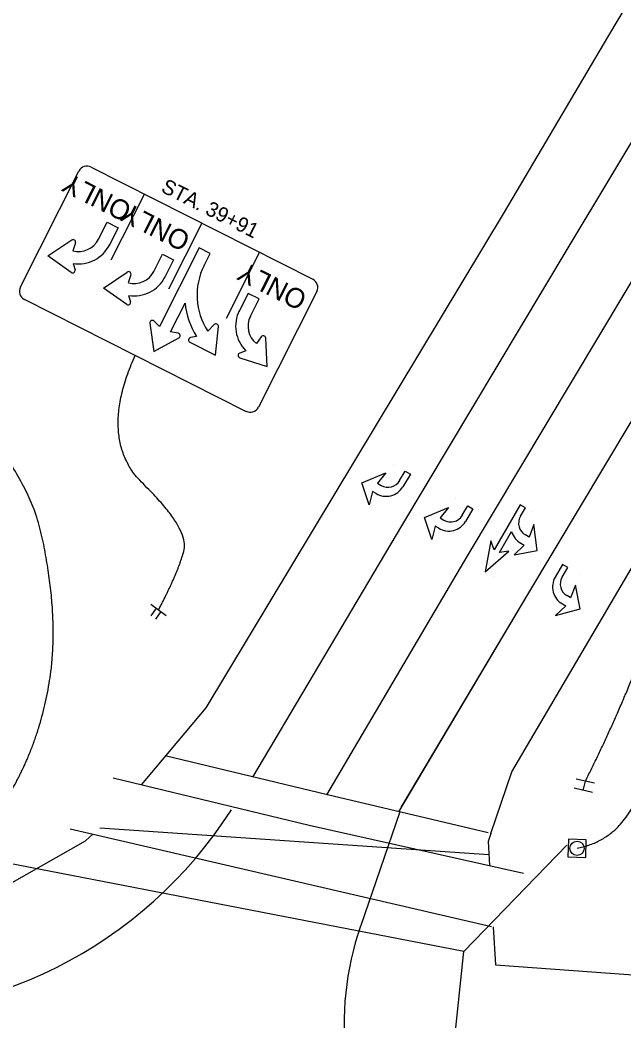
# Model space of a CAD drawing. Extents: x 1847379 to 1850904, y 217032 to 220169.
# Drawn here: x 1848879.8 to 1848981.8, y 218877.1 to 219045.9 of the extents above; entities that cross this region are included whole.
import ezdxf

# ---------------------------------------------------------------- set-up
doc = ezdxf.new("R2010")
doc.units = 0
for name, color, linetype in [('BR_P_Gen_Approach_Slab_Hidden', 7, 'Continuous'), ('BR_P_Gen_Phase_Construction', 7, 'Continuous'), ('PM_P_Cells', 7, 'Continuous'), ('PM_P_Crosswalk', 7, 'Continuous'), ('PM_P_Dotted_Line', 7, 'Continuous'), ('PM_P_Edge_Line', 7, 'Continuous'), ('PM_P_Stop_Line', 7, 'Continuous'), ('PM_X_Cells', 7, 'Continuous'), ('PM_X_Channelizing_Line', 7, 'Continuous'), ('PM_X_Dotted_Line', 7, 'Continuous'), ('PM_X_Stop_Line', 7, 'Continuous'), ('SG_X_Wiring', 7, 'Continuous'), ('SN_X_Foundation', 7, 'Continuous'), ('SN_X_Public', 7, 'Continuous')]:
    doc.layers.add(name, color=color, linetype=linetype)

msp = doc.modelspace()

# ---------------------------------------------------------------- linework, layer by layer
at = {"layer": 'BR_P_Gen_Approach_Slab_Hidden'}
for p, q in [((1848979.04, 219043.04), (1849023.78, 219117.99)), ((1848961.59, 219013.49), (1848979.04, 219043.04)), ((1848911.24, 218929.86), (1848961.59, 219013.49)), ((1848962.84, 218919.07), (1849001.98, 218985.74)), ((1848900.33, 218916.9), (1848911.24, 218929.86)), ((1848959.3, 218908.69), (1848962.84, 218919.07)), ((1848959.3, 218908.69), (1848958.84, 218907.32)), ((1848958.84, 218907.32), (1848959.08, 218903.27))]:
    msp.add_line(p, q, dxfattribs=at)
at = {"layer": 'BR_P_Gen_Phase_Construction'}
msp.add_line((1848893.29, 218909.66), (1848958.97, 218905.12), dxfattribs=at)
at = {"layer": 'PM_P_Cells'}
for p, q in [((1848964.26, 218964.14), (1848959.88, 218956.56)), ((1848965.13, 218963.64), (1848964.26, 218964.14)), ((1848964.29, 218962.19), (1848965.13, 218963.64)), ((1848966.14, 218963.05), (1848966.14, 218963.05)), ((1848966.57, 218960.81), (1848965.74, 218958.7)), ((1848967.12, 218956.42), (1848966.57, 218960.81)), ((1848965.74, 218958.7), (1848965.13, 218959.05)), ((1848959.31, 218958.04), (1848958.32, 218952.85)), ((1848959.88, 218956.56), (1848959.31, 218958.04)), ((1848964.94, 218957.31), (1848963.24, 218955.71)), ((1848964.36, 218957.65), (1848964.94, 218957.31)), ((1848958.32, 218952.85), (1848962.32, 218956.31)), ((1848962.32, 218956.31), (1848960.75, 218956.06)), ((1848963.24, 218955.71), (1848967.12, 218956.42)), ((1848959.76, 218952.01), (1848959.76, 218952.01))]:
    msp.add_line(p, q, dxfattribs=at)
msp.add_lwpolyline([(1848960.75, 218956.06), (1848962.8, 218959.61)], dxfattribs=at)
for centre, radius, start, end in [((1848966.28, 218961.04), 2.3, 149.9979, 239.9979), ((1848965.96, 218960.51), 3.28, 195.9514, 240.9064)]:
    msp.add_arc(centre, radius, start, end, dxfattribs=at)
at = {"layer": 'PM_P_Crosswalk'}
msp.add_line((1848888.3, 218909.46), (1848959.41, 218892.97), dxfattribs=at)
msp.add_lwpolyline([(1848895.52, 218918.05), (1848928.63, 218910.1), (1848964.8, 218901.99)], dxfattribs=at)
at = {"layer": 'PM_P_Dotted_Line'}
msp.add_line((1848943.92, 218912.31), (1848937.27, 218893.02), dxfattribs=at)
for centre, radius, start, end in [((1848852.35, 218953.13), 75, 265.9117, 327.3396), ((1848984.54, 218876.73), 50, 160.9794, 265.9392)]:
    msp.add_arc(centre, radius, start, end, dxfattribs=at)
at = {"layer": 'PM_P_Edge_Line'}
for p, q in [((1848890.9, 218907.47), (1848892.11, 218908.58)), ((1848871.96, 218896.75), (1848890.9, 218907.47)), ((1848960.09, 218886.51), (1849497.6, 218848.14))]:
    msp.add_line(p, q, dxfattribs=at)
at = {"layer": 'PM_P_Stop_Line'}
msp.add_lwpolyline([(1848958.83, 218908.8), (1848931.71, 218915.18), (1848904.32, 218921.76)], dxfattribs=at)
at = {"layer": 'PM_X_Cells'}
for p, q in [((1848942.83, 218971.01), (1848942.83, 218971.01)), ((1848937.49, 218967.84), (1848941.57, 218969.53)), ((1848941.57, 218969.53), (1848940.15, 218967.76)), ((1848943.9, 218968.23), (1848944.84, 218969.83)), ((1848945.71, 218969.33), (1848944.45, 218967.19)), ((1848944.84, 218969.83), (1848945.71, 218969.33)), ((1848938.78, 218964.12), (1848937.49, 218967.84)), ((1848940.15, 218967.76), (1848940.76, 218967.41)), ((1848939.34, 218966.38), (1848938.78, 218964.12)), ((1848939.91, 218966.05), (1848939.34, 218966.38)), ((1848938.78, 218964.12), (1848938.78, 218964.12)), ((1848948.07, 218961.99), (1848952.15, 218963.67)), ((1848952.15, 218963.67), (1848950.73, 218961.91)), ((1848953.41, 218965.16), (1848953.41, 218965.16)), ((1848954.48, 218962.37), (1848955.42, 218963.98)), ((1848955.42, 218963.98), (1848956.28, 218963.47)), ((1848949.36, 218958.26), (1848948.07, 218961.99)), ((1848956.28, 218963.47), (1848955.03, 218961.33)), ((1848949.92, 218960.53), (1848949.36, 218958.26)), ((1848950.49, 218960.19), (1848949.92, 218960.53)), ((1848950.73, 218961.91), (1848951.34, 218961.55)), ((1848949.36, 218958.26), (1848949.36, 218958.26)), ((1848971.41, 218954.07), (1848970.15, 218951.93)), ((1848971.33, 218951.95), (1848972.27, 218953.56)), ((1848972.27, 218953.56), (1848971.41, 218954.07)), ((1848974.28, 218952.38), (1848974.28, 218952.38)), ((1848973.6, 218950.55), (1848972.75, 218948.45)), ((1848974.36, 218946.58), (1848973.6, 218950.55)), ((1848972.75, 218948.45), (1848972.15, 218948.81)), ((1848971.94, 218947.07), (1848970.23, 218945.48)), ((1848971.37, 218947.41), (1848971.94, 218947.07)), ((1848970.23, 218945.48), (1848974.36, 218946.58)), ((1848970.23, 218945.48), (1848970.23, 218945.48))]:
    msp.add_line(p, q, dxfattribs=at)
for centre, radius, start, end in [((1848941.62, 218968.85), 3.28, 238.6655, 329.574), ((1848941.92, 218969.39), 2.3, 239.574, 329.574), ((1848952.5, 218963.53), 2.3, 239.574, 329.574), ((1848952.2, 218962.99), 3.28, 238.6655, 329.574), ((1848972.98, 218950.27), 3.28, 149.574, 240.4825), ((1848973.31, 218950.79), 2.3, 149.574, 239.574)]:
    msp.add_arc(centre, radius, start, end, dxfattribs=at)
at = {"layer": 'PM_X_Channelizing_Line'}
for points in [[(1848919.1, 218918.16), (1848944.27, 218960.56), (1848972.34, 219007.48), (1849015.24, 219078.84), (1849034.6, 219111.78), (1849062.58, 219158.93), (1849078.71, 219187.23), (1849099.56, 219230.42), (1849123.53, 219290.46)], [(1848931.59, 218915.21), (1848955.27, 218955.41), (1848981.8, 218999.65), (1849029.93, 219080.35), (1849061.68, 219133.31), (1849077.82, 219161.54), (1849103.89, 219209.58), (1849122.08, 219251.34), (1849135.29, 219287.48)], [(1848943.75, 218912.35), (1848965.51, 218949.03), (1848991.71, 218992.7), (1849039.97, 219073.89), (1849071.48, 219127.17)]]:
    msp.add_lwpolyline(points, dxfattribs=at)
at = {"layer": 'PM_X_Dotted_Line'}
msp.add_line((1848944.24, 218913.18), (1848965.51, 218949.03), dxfattribs=at)
at = {"layer": 'PM_X_Stop_Line'}
msp.add_line((1848959.7, 218892.91), (1848960.09, 218886.51), dxfattribs=at)
at = {"layer": 'SG_X_Wiring'}
for p, q in [((1848954.76, 218888.78), (1848853.47, 218908.37)), ((1848954.76, 218888.78), (1848972.11, 218906.71)), ((1848945.32, 218800.54), (1848954.76, 218888.78))]:
    msp.add_line(p, q, dxfattribs=at)
at = {"layer": 'SN_X_Foundation'}
msp.add_lwpolyline([(1848975.3, 218904.63), (1848975.4, 218907.63), (1848972.4, 218907.74), (1848972.3, 218904.74)], close=True, dxfattribs=at)
msp.add_circle((1848973.85, 218906.18), 1.2, dxfattribs=at)
at = {"layer": 'SN_X_Public'}
for p, q in [((1848900.82, 219016.57), (1848895.18, 219005.41)), ((1848893.05, 219008.93), (1848894.51, 219011.82)), ((1848894.51, 219011.82), (1848896.37, 219010.88)), ((1848910.53, 219011.66), (1848904.9, 219000.5)), ((1848896.37, 219010.88), (1848894.79, 219007.76)), ((1848884.52, 219006.13), (1848888.55, 219008.81)), ((1848889.17, 219008.33), (1848888.73, 219007)), ((1848894.79, 219007.76), (1848894.92, 219007.99)), ((1848888.47, 219003.33), (1848884.52, 219006.13)), ((1848902.42, 219003.52), (1848903.88, 219006.4)), ((1848910.06, 219007.48), (1848903.37, 218994.24)), ((1848903.88, 219006.4), (1848905.74, 219005.46)), ((1848911.92, 219006.54), (1848910.06, 219007.48)), ((1848910.88, 219004.49), (1848911.92, 219006.54)), ((1848920.25, 219006.75), (1848914.62, 218995.59)), ((1848888.79, 219004.86), (1848889.11, 219003.79)), ((1848905.74, 219005.46), (1848904.16, 219002.34)), ((1848893.89, 219000.71), (1848897.91, 219003.39)), ((1848898.54, 219002.92), (1848898.1, 219001.59)), ((1848904.16, 219002.34), (1848904.29, 219002.57)), ((1848897.84, 218997.92), (1848893.89, 219000.71)), ((1848898.16, 218999.44), (1848898.48, 218998.37)), ((1848918.31, 218999.79), (1848916.74, 218996.67)), ((1848920.17, 218998.86), (1848918.31, 218999.79)), ((1848905.23, 218993.3), (1848907.68, 218998.16)), ((1848918.72, 218995.97), (1848920.17, 218998.86)), ((1848916.74, 218996.67), (1848916.85, 218996.91)), ((1848901.74, 218994.78), (1848902.39, 218989.99)), ((1848903.37, 218994.24), (1848902.44, 218995.13)), ((1848912.59, 218994.53), (1848911.53, 218993.42)), ((1848912.82, 218989.39), (1848913.31, 218994.19)), ((1848906.5, 218993.09), (1848905.23, 218993.3)), ((1848909.62, 218992.54), (1848908.61, 218992.34)), ((1848920.54, 218992.49), (1848919.72, 218991.35)), ((1848902.39, 218989.99), (1848906.63, 218992.31)), ((1848908.51, 218991.56), (1848912.82, 218989.39)), ((1848921.52, 218987.44), (1848921.29, 218992.27)), ((1848917.96, 218990.12), (1848916.92, 218989.74)), ((1848916.93, 218988.95), (1848921.52, 218987.44)), ((1848901.92, 218947.35), (1848904.52, 218945.48)), ((1848902.83, 218946.7), (1848901.89, 218945.4)), ((1848903.61, 218946.14), (1848902.67, 218944.84)), ((1848903.22, 218946.42), (1848903.22, 218946.42)), ((1848976.81, 218917.16), (1848973.69, 218917.87)), ((1848974.89, 218915.96), (1848975.25, 218917.52)), ((1848975.07, 218916.74), (1848975.07, 218916.74)), ((1848976.45, 218915.6), (1848973.33, 218916.31))]:
    msp.add_line(p, q, dxfattribs=at)
for points in [[(1848891.85, 219021.1), (1848929.22, 219002.22)], [(1848879.89, 219000.89), (1848889.75, 219020.41)], [(1848929.91, 219000.12), (1848920.05, 218980.59)], [(1848917.95, 218979.9), (1848880.58, 218998.79)]]:
    msp.add_lwpolyline(points, dxfattribs=at)
for centre, radius, start, end in [((1848891.14, 219019.71), 1.56, 63.1962, 153.1962), ((1848888.78, 219008.46), 0.417, 341.8109, 123.689), ((1848889.71, 219010.62), 3.75, 254.973, 333.1962), ((1848889.71, 219010.62), 5.84, 260.9642, 333.1962), ((1848920.74, 218999.51), 11.04, 153.1962, 213.4878), ((1848888.71, 219003.67), 0.417, 234.6564, 16.5345), ((1848898.15, 219003.05), 0.417, 341.8109, 123.689), ((1848899.08, 219005.21), 3.75, 254.973, 333.1962), ((1848899.08, 219005.21), 5.84, 260.9642, 333.1962), ((1848881.28, 219000.18), 1.56, 153.1962, 243.1962), ((1848928.52, 219000.82), 1.56, 333.1962, 63.1962), ((1848898.08, 218998.26), 0.417, 234.6564, 16.5345), ((1848920.74, 218999.51), 13.13, 185.9213, 212.0639), ((1848922.06, 218994.28), 5.84, 153.1962, 225.4282), ((1848922.06, 218994.28), 3.75, 153.1962, 231.4195), ((1848902.15, 218994.83), 0.417, 45.8344, 187.7125), ((1848912.89, 218994.24), 0.417, 354.2034, 136.0815), ((1848906.43, 218992.67), 0.417, 298.6799, 80.558), ((1848920.88, 218992.25), 0.417, 2.7034, 144.5815), ((1848908.69, 218991.93), 0.417, 101.3579, 243.236), ((1848917.06, 218989.35), 0.417, 109.8579, 251.736), ((1848918.66, 218981.3), 1.56, 243.1962, 333.1962)]:
    msp.add_arc(centre, radius, start, end, dxfattribs=at)
for points in [[(1848877.68, 218914.76), (1848882.95, 218923.3), (1848886.59, 218944.99), (1848880.24, 218973.57), (1848860.7, 218989.49)], [(1848903.22, 218946.42), (1848906.39, 218952.46), (1848908.51, 218960), (1848892.88, 218975.12), (1848899.26, 218989.35)], [(1848975.25, 218917.52), (1848982.89, 218932.61), (1848996.11, 218970.77), (1849017.02, 218994.94), (1849025.47, 218987.85)], [(1848973.85, 218906.18), (1848984.63, 218908.32), (1848987.82, 218939.63), (1849002.17, 218936.22)]]:
    msp.add_open_spline(points, degree=2, dxfattribs=at)

# ---------------------------------------------------------------- texts
for s, height, rotation, p in [('ONLY', 3.333, 153.1962, (1848898.94, 219014.72)), ('STA. 39+91', 2.5, 333.1962, (1848903.46, 219017.02)), ('ONLY', 3.333, 153.1962, (1848908.83, 219009.72)), ('ONLY', 3.333, 153.1962, (1848928.53, 218999.77))]:
    msp.add_text(s, height=height, rotation=rotation, dxfattribs=at).set_placement(p)

doc.saveas('drawing.dxf')
